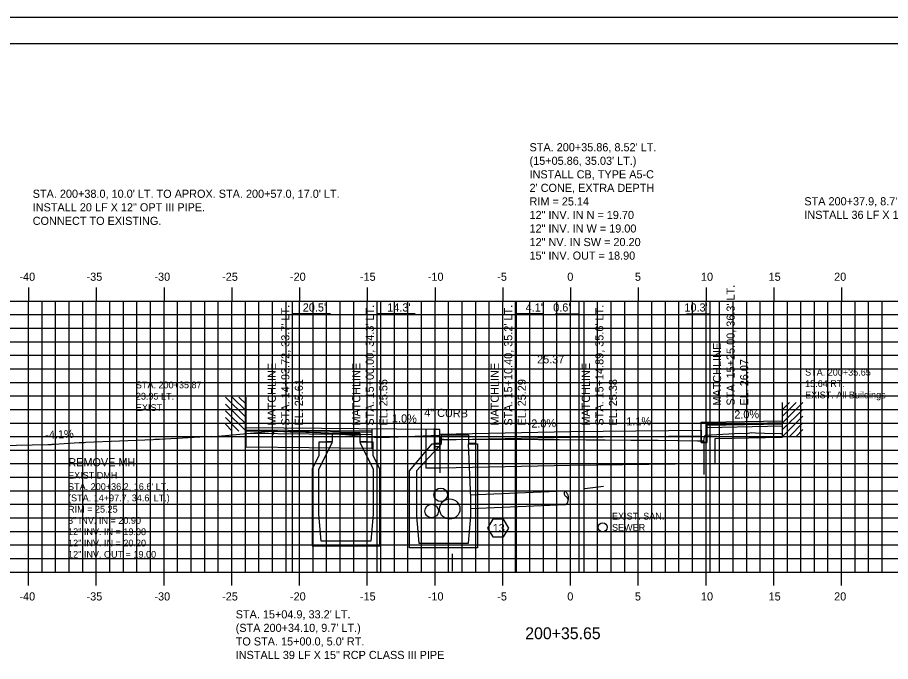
# Model space of a CAD drawing. Extents: x 1023237 to 1023407, y 394697 to 394807.
# Drawn here: x 1023278.8 to 1023343.3, y 394759 to 394806.5 of the extents above; entities that cross this region are included whole.
import ezdxf

# ---------------------------------------------------------------- set-up
doc = ezdxf.new("R2010")
doc.units = 0
for name, color, linetype in [('ANNOTATION', 7, 'Continuous'), ('BORDER', 7, 'Continuous'), ('D_Curb_Type_1_Lt', 7, 'Continuous'), ('D_Curb_Type_1_Rt', 7, 'Continuous'), ('D_Drainage_CB_Shape5_Lt', 7, 'Continuous'), ('D_Drainage_Culvert', 7, 'Continuous'), ('D_Drainage_Text', 7, 'Continuous'), ('D_Roadway_Centerline', 7, 'Continuous'), ('D_Roadway_Centerline_Text', 7, 'Continuous'), ('D_Roadway_Edge_TW', 7, 'Continuous'), ('D_Roadway_Sidewalks_Paved', 7, 'Continuous'), ('D_Roadway_SubGrade', 7, 'Continuous'), ('D_Text_Monospaced', 7, 'Continuous'), ('H_V ANNOTATION', 7, 'Continuous'), ('MAJOR', 7, 'Continuous'), ('MINOR', 7, 'Continuous'), ('PLOT BOUNDARY', 7, 'Continuous'), ('S_Buildings_SillElevation', 7, 'Continuous'), ('S_Roadway_Centerline', 7, 'Continuous'), ('S_Roadway_Edge_Pavement', 7, 'Continuous'), ('S_Utilities_UG_Sanitary_MH', 7, 'Continuous'), ('S_Utilities_UG_Sanitary_Sewer', 7, 'Continuous')]:
    doc.layers.add(name, color=color, linetype=linetype)

msp = doc.modelspace()

# ---------------------------------------------------------------- linework, layer by layer
at = {"layer": 'ANNOTATION'}
for p, q in [((1023299.149, 394765.607), (1023299.149, 394785.607)), ((1023305.384, 394765.607), (1023305.384, 394785.607)), ((1023315.6, 394765.607), (1023315.6, 394785.607)), ((1023320.296, 394765.607), (1023320.296, 394785.607)), ((1023329.979, 394765.607), (1023329.979, 394785.607)), ((1023301.955, 394784.658), (1023299.149, 394784.658)), ((1023308.19, 394784.658), (1023305.384, 394784.658)), ((1023317.591, 394784.658), (1023315.6, 394784.658)), ((1023318.531, 394784.658), (1023320.296, 394784.658)), ((1023328.214, 394784.658), (1023329.979, 394784.658)), ((1023322.088, 394771.909), (1023320.706, 394771.748)), ((1023310.935, 394766.95), (1023310.935, 394765.674))]:
    msp.add_line(p, q, dxfattribs=at)
at = {"layer": 'BORDER'}
msp.add_line((1023404.664, 394804.607), (1023244.664, 394804.607), dxfattribs=at)
at = {"layer": 'D_Curb_Type_1_Lt'}
msp.add_lwpolyline([(1023310.015, 394776.118), (1023309.599, 394776.118), (1023309.599, 394774.618), (1023310.015, 394774.618), (1023310.015, 394775.535), (1023310.015, 394776.118)], dxfattribs=at)
msp.add_lwpolyline([(1023310.015, 394776.118), (1023309.599, 394776.118), (1023309.599, 394774.618), (1023310.015, 394774.618), (1023310.015, 394775.535), (1023310.015, 394776.118)], dxfattribs=at)
msp.add_lwpolyline([(1023309.599, 394776.118), (1023309.599, 394774.618), (1023310.015, 394774.618), (1023310.015, 394776.118)], close=True, dxfattribs=at)
at = {"layer": 'D_Curb_Type_1_Rt'}
msp.add_lwpolyline([(1023329.309, 394776.668), (1023329.726, 394776.668), (1023329.726, 394775.168), (1023329.309, 394775.168), (1023329.309, 394776.084), (1023329.309, 394776.668)], dxfattribs=at)
msp.add_lwpolyline([(1023329.726, 394776.668), (1023329.726, 394775.168), (1023329.309, 394775.168), (1023329.309, 394776.668)], close=True, dxfattribs=at)
at = {"layer": 'D_Drainage_CB_Shape5_Lt'}
for points in [[(1023309.615, 394775.121), (1023310.14, 394775.121), (1023310.14, 394775.745), (1023312.141, 394775.745), (1023312.141, 394775.121), (1023312.633, 394775.121)], [(1023312.797, 394775.08), (1023312.797, 394767.402), (1023307.778, 394767.402), (1023307.778, 394773.077), (1023309.451, 394775.08), (1023310.14, 394775.08), (1023308.303, 394773.077), (1023308.303, 394769.732), (1023308.467, 394767.73), (1023312.141, 394767.73), (1023312.305, 394769.732), (1023312.305, 394771.077), (1023312.141, 394775.08), (1023312.797, 394775.08)]]:
    msp.add_lwpolyline(points, dxfattribs=at)
at = {"layer": 'D_Drainage_Culvert'}
for p, q in [((1023312.244, 394771.305), (1023319.24, 394771.592)), ((1023312.305, 394770.307), (1023319.301, 394770.593))]:
    msp.add_line(p, q, dxfattribs=at)
for centre, radius in [((1023310.084, 394771.307), 0.5), ((1023309.41, 394770.107), 0.5), ((1023310.747, 394770.257), 0.75)]:
    msp.add_circle(centre, radius, dxfattribs=at)
for centre, radius, start, end in [((1023319.477, 394771.426), 0.289, 145.08411, 241.23563), ((1023318.882, 394771.066), 0.636, 342.2646, 55.76139), ((1023319.153, 394770.893), 0.335, 296.14952, 56.63552)]:
    msp.add_arc(centre, radius, start, end, dxfattribs=at)
at = {"layer": 'D_Drainage_Text'}
msp.add_lwpolyline([(1023315.115, 394768.854), (1023314.718, 394769.503), (1023313.925, 394769.503), (1023313.528, 394768.854), (1023313.925, 394768.205), (1023314.718, 394768.205)], close=True, dxfattribs=at)
at = {"layer": 'D_Roadway_Edge_TW'}
for p, q in [((1023309.599, 394776.118), (1023295.715, 394776.255)), ((1023295.715, 394774.813), (1023295.715, 394776.255)), ((1023305.014, 394775.997), (1023295.715, 394776.089)), ((1023305.014, 394775.913), (1023295.715, 394776.005)), ((1023305.014, 394775.747), (1023295.715, 394775.839)), ((1023305.014, 394774.714), (1023305.014, 394776.157)), ((1023310.015, 394775.785), (1023319.663, 394775.982)), ((1023310.015, 394775.535), (1023310.015, 394775.785)), ((1023319.663, 394775.982), (1023329.309, 394776.084)), ((1023329.309, 394776.084), (1023329.309, 394775.834)), ((1023305.014, 394774.721), (1023295.715, 394774.813))]:
    msp.add_line(p, q, dxfattribs=at)
at = {"layer": 'D_Roadway_Sidewalks_Paved'}
for p, q in [((1023329.726, 394776.668), (1023335.307, 394776.779)), ((1023329.726, 394776.501), (1023329.726, 394776.668)), ((1023335.307, 394776.613), (1023329.726, 394776.501)), ((1023335.307, 394776.529), (1023329.726, 394776.418)), ((1023335.307, 394776.363), (1023329.726, 394776.251)), ((1023335.307, 394775.529), (1023330.309, 394775.429))]:
    msp.add_line(p, q, dxfattribs=at)
at = {"layer": 'D_Roadway_SubGrade'}
for p, q in [((1023309.599, 394776.201), (1023309.599, 394774.868)), ((1023329.726, 394776.501), (1023334.309, 394776.593)), ((1023329.726, 394775.168), (1023329.726, 394776.501)), ((1023305.015, 394775.157), (1023305.015, 394776.157)), ((1023309.015, 394773.265), (1023309.015, 394776.124)), ((1023310.015, 394775.368), (1023319.663, 394775.565)), ((1023310.015, 394774.868), (1023310.015, 394775.535)), ((1023310.015, 394775.535), (1023310.015, 394775.285)), ((1023319.663, 394775.565), (1023329.309, 394775.668)), ((1023329.309, 394775.584), (1023329.309, 394775.834)), ((1023329.309, 394775.834), (1023329.309, 394775.168)), ((1023329.309, 394775.168), (1023329.726, 394775.168)), ((1023330.309, 394775.429), (1023330.309, 394773.564)), ((1023309.599, 394774.868), (1023310.015, 394774.868)), ((1023310.015, 394773.285), (1023309.015, 394773.265)), ((1023319.663, 394773.482), (1023310.015, 394773.285)), ((1023329.309, 394773.584), (1023319.663, 394773.482)), ((1023330.309, 394773.564), (1023329.309, 394773.584))]:
    msp.add_line(p, q, dxfattribs=at)
at = {"layer": 'MAJOR'}
for p, q in [((1023279.663, 394786.609), (1023279.663, 394785.607)), ((1023284.663, 394786.609), (1023284.663, 394785.607)), ((1023289.663, 394786.609), (1023289.663, 394785.607)), ((1023294.663, 394786.609), (1023294.663, 394785.607)), ((1023299.663, 394786.609), (1023299.663, 394785.607)), ((1023304.663, 394786.609), (1023304.663, 394785.607)), ((1023309.663, 394786.609), (1023309.663, 394785.607)), ((1023314.663, 394786.609), (1023314.663, 394785.607)), ((1023319.663, 394786.609), (1023319.663, 394785.607)), ((1023324.663, 394786.609), (1023324.663, 394785.607)), ((1023329.663, 394786.609), (1023329.663, 394785.607)), ((1023334.663, 394786.609), (1023334.663, 394785.607)), ((1023339.663, 394786.609), (1023339.663, 394785.607)), ((1023249.663, 394785.607), (1023389.663, 394785.607)), ((1023279.663, 394765.607), (1023279.663, 394785.607)), ((1023284.663, 394765.607), (1023284.663, 394785.607)), ((1023289.663, 394765.607), (1023289.663, 394785.607)), ((1023294.663, 394765.607), (1023294.663, 394785.607)), ((1023299.663, 394765.607), (1023299.663, 394785.607)), ((1023304.663, 394765.607), (1023304.663, 394785.607)), ((1023309.663, 394765.607), (1023309.663, 394785.607)), ((1023314.663, 394765.607), (1023314.663, 394785.607)), ((1023319.663, 394765.607), (1023319.663, 394785.607)), ((1023324.663, 394765.607), (1023324.663, 394785.607)), ((1023329.663, 394765.607), (1023329.663, 394785.607)), ((1023334.663, 394765.607), (1023334.663, 394785.607)), ((1023339.663, 394765.607), (1023339.663, 394785.607)), ((1023249.663, 394780.607), (1023389.663, 394780.607)), ((1023249.663, 394775.607), (1023389.663, 394775.607)), ((1023249.663, 394770.607), (1023389.663, 394770.607)), ((1023249.663, 394765.607), (1023389.663, 394765.607)), ((1023279.663, 394764.605), (1023279.663, 394765.607)), ((1023284.663, 394764.605), (1023284.663, 394765.607)), ((1023289.663, 394764.605), (1023289.663, 394765.607)), ((1023294.663, 394764.605), (1023294.663, 394765.607)), ((1023299.663, 394764.605), (1023299.663, 394765.607)), ((1023304.663, 394764.605), (1023304.663, 394765.607)), ((1023309.663, 394764.605), (1023309.663, 394765.607)), ((1023314.663, 394764.605), (1023314.663, 394765.607)), ((1023319.663, 394764.605), (1023319.663, 394765.607)), ((1023324.663, 394764.605), (1023324.663, 394765.607)), ((1023329.663, 394764.605), (1023329.663, 394765.607)), ((1023334.663, 394764.605), (1023334.663, 394765.607)), ((1023339.663, 394764.605), (1023339.663, 394765.607))]:
    msp.add_line(p, q, dxfattribs=at)
at = {"layer": 'MINOR'}
for p, q in [((1023280.663, 394765.607), (1023280.663, 394785.607)), ((1023281.663, 394765.607), (1023281.663, 394785.607)), ((1023282.663, 394765.607), (1023282.663, 394785.607)), ((1023283.663, 394765.607), (1023283.663, 394785.607)), ((1023285.663, 394765.607), (1023285.663, 394785.607)), ((1023286.663, 394765.607), (1023286.663, 394785.607)), ((1023287.663, 394765.607), (1023287.663, 394785.607)), ((1023288.663, 394765.607), (1023288.663, 394785.607)), ((1023290.663, 394765.607), (1023290.663, 394785.607)), ((1023291.663, 394765.607), (1023291.663, 394785.607)), ((1023292.663, 394765.607), (1023292.663, 394785.607)), ((1023293.663, 394765.607), (1023293.663, 394785.607)), ((1023295.663, 394765.607), (1023295.663, 394785.607)), ((1023296.663, 394765.607), (1023296.663, 394785.607)), ((1023297.663, 394765.607), (1023297.663, 394785.607)), ((1023298.663, 394765.607), (1023298.663, 394785.607)), ((1023300.663, 394765.607), (1023300.663, 394785.607)), ((1023301.663, 394765.607), (1023301.663, 394785.607)), ((1023302.663, 394765.607), (1023302.663, 394785.607)), ((1023303.663, 394765.607), (1023303.663, 394785.607)), ((1023305.663, 394765.607), (1023305.663, 394785.607)), ((1023306.663, 394765.607), (1023306.663, 394785.607)), ((1023307.663, 394765.607), (1023307.663, 394785.607)), ((1023308.663, 394765.607), (1023308.663, 394785.607)), ((1023310.663, 394765.607), (1023310.663, 394785.607)), ((1023311.663, 394765.607), (1023311.663, 394785.607)), ((1023312.663, 394765.607), (1023312.663, 394785.607)), ((1023313.663, 394765.607), (1023313.663, 394785.607)), ((1023315.663, 394765.607), (1023315.663, 394785.607)), ((1023316.663, 394765.607), (1023316.663, 394785.607)), ((1023317.663, 394765.607), (1023317.663, 394785.607)), ((1023318.663, 394765.607), (1023318.663, 394785.607)), ((1023320.663, 394765.607), (1023320.663, 394785.607)), ((1023321.663, 394765.607), (1023321.663, 394785.607)), ((1023322.663, 394765.607), (1023322.663, 394785.607)), ((1023323.663, 394765.607), (1023323.663, 394785.607)), ((1023325.663, 394765.607), (1023325.663, 394785.607)), ((1023326.663, 394765.607), (1023326.663, 394785.607)), ((1023327.663, 394765.607), (1023327.663, 394785.607)), ((1023328.663, 394765.607), (1023328.663, 394785.607)), ((1023330.663, 394765.607), (1023330.663, 394785.607)), ((1023331.663, 394765.607), (1023331.663, 394785.607)), ((1023332.663, 394765.607), (1023332.663, 394785.607)), ((1023333.663, 394765.607), (1023333.663, 394785.607)), ((1023335.663, 394765.607), (1023335.663, 394785.607)), ((1023336.663, 394765.607), (1023336.663, 394785.607)), ((1023337.663, 394765.607), (1023337.663, 394785.607)), ((1023338.663, 394765.607), (1023338.663, 394785.607)), ((1023340.663, 394765.607), (1023340.663, 394785.607)), ((1023341.663, 394765.607), (1023341.663, 394785.607)), ((1023342.663, 394765.607), (1023342.663, 394785.607)), ((1023249.663, 394784.607), (1023389.663, 394784.607)), ((1023249.663, 394783.607), (1023389.663, 394783.607)), ((1023249.663, 394782.607), (1023389.663, 394782.607)), ((1023249.663, 394781.607), (1023389.663, 394781.607)), ((1023249.663, 394779.607), (1023389.663, 394779.607)), ((1023249.663, 394778.607), (1023389.663, 394778.607)), ((1023249.663, 394777.607), (1023389.663, 394777.607)), ((1023249.663, 394776.607), (1023389.663, 394776.607)), ((1023249.663, 394774.607), (1023389.663, 394774.607)), ((1023249.663, 394773.607), (1023389.663, 394773.607)), ((1023249.663, 394772.607), (1023389.663, 394772.607)), ((1023249.663, 394771.607), (1023389.663, 394771.607)), ((1023249.663, 394769.607), (1023389.663, 394769.607)), ((1023249.663, 394768.607), (1023389.663, 394768.607)), ((1023249.663, 394767.607), (1023389.663, 394767.607)), ((1023249.663, 394766.607), (1023389.663, 394766.607))]:
    msp.add_line(p, q, dxfattribs=at)
at = {"layer": 'PLOT BOUNDARY'}
msp.add_lwpolyline([(1023236.57, 394696.548), (1023406.57, 394696.548), (1023406.57, 394806.548), (1023236.57, 394806.548)], close=True, dxfattribs=at)
at = {"layer": 'S_Buildings_SillElevation'}
for p, q in [((1023295.715, 394777.019), (1023294.206, 394778.528)), ((1023295.715, 394777.511), (1023294.698, 394778.528)), ((1023295.715, 394778.003), (1023295.19, 394778.528)), ((1023295.715, 394776.002), (1023295.715, 394778.528)), ((1023335.307, 394775.607), (1023335.307, 394778.133)), ((1023335.307, 394776.624), (1023336.816, 394778.133)), ((1023335.307, 394777.116), (1023336.324, 394778.133)), ((1023335.307, 394777.608), (1023335.832, 394778.133)), ((1023295.715, 394776.527), (1023294.206, 394778.003)), ((1023295.715, 394776.002), (1023294.206, 394777.511)), ((1023335.307, 394776.132), (1023336.816, 394777.608)), ((1023295.19, 394776.002), (1023294.206, 394777.019)), ((1023335.307, 394775.607), (1023336.816, 394777.116)), ((1023294.698, 394776.002), (1023294.206, 394776.527)), ((1023335.832, 394775.607), (1023336.816, 394776.624)), ((1023336.324, 394775.607), (1023336.816, 394776.132))]:
    msp.add_line(p, q, dxfattribs=at)
at = {"layer": 'S_Roadway_Centerline'}
msp.add_lwpolyline([(1023275.244, 394774.892), (1023281.097, 394775.028), (1023281.202, 394775.03), (1023281.204, 394775.03), (1023281.343, 394775.033), (1023281.344, 394775.033), (1023281.403, 394775.037), (1023281.437, 394775.039), (1023281.545, 394775.046), (1023283.396, 394775.162), (1023283.774, 394775.179), (1023283.902, 394775.184), (1023288.867, 394775.402), (1023288.972, 394775.407), (1023289.317, 394775.423), (1023293.139, 394775.63), (1023293.14, 394775.599), (1023293.244, 394775.612), (1023293.378, 394775.619), (1023293.504, 394775.622), (1023293.529, 394775.623), (1023293.666, 394775.628), (1023297.635, 394775.997), (1023297.693, 394776.003), (1023297.693, 394775.801), (1023297.759, 394775.803), (1023297.759, 394776.004), (1023298.028, 394776.003), (1023298.969, 394775.969), (1023299.566, 394775.947), (1023302.375, 394775.844), (1023304.669, 394775.583), (1023305.682, 394775.53), (1023307.546, 394775.616), (1023309.977, 394775.718), (1023310.015, 394775.424), (1023310.03, 394775.423), (1023310.282, 394775.414), (1023311.06, 394775.391), (1023311.102, 394775.389), (1023313.244, 394775.404), (1023317.309, 394775.388), (1023318.818, 394775.396), (1023320.803, 394775.378), (1023322.217, 394775.362), (1023324.111, 394775.336), (1023326.127, 394775.33), (1023329.023, 394775.301), (1023329.498, 394775.302), (1023329.542, 394775.585), (1023329.597, 394775.723), (1023332.207, 394775.857), (1023332.619, 394775.837), (1023333.033, 394775.898), (1023333.309, 394775.889), (1023333.98, 394775.867), (1023335.158, 394775.828), (1023335.249, 394775.827), (1023335.307, 394775.826)], dxfattribs=at)
at = {"layer": 'S_Roadway_Edge_Pavement'}
for p, q in [((1023310.015, 394775.424), (1023310.015, 394772.924)), ((1023329.498, 394775.302), (1023329.498, 394772.802))]:
    msp.add_line(p, q, dxfattribs=at)
at = {"layer": 'S_Utilities_UG_Sanitary_MH'}
for p, q in [((1023301.087, 394773.193), (1023302.105, 394775.194)), ((1023302.105, 394775.194), (1023301.087, 394775.194)), ((1023301.087, 394775.194), (1023301.087, 394774.21)), ((1023305.09, 394775.194), (1023304.106, 394775.194)), ((1023304.106, 394775.194), (1023305.09, 394773.193)), ((1023305.09, 394774.21), (1023305.09, 394775.194)), ((1023301.087, 394774.21), (1023300.595, 394773.193)), ((1023305.582, 394773.193), (1023305.09, 394774.21)), ((1023300.595, 394773.193), (1023300.595, 394767.55)), ((1023301.087, 394769.879), (1023301.087, 394773.193)), ((1023305.09, 394773.193), (1023305.09, 394769.879)), ((1023305.582, 394767.55), (1023305.582, 394773.193)), ((1023301.251, 394767.878), (1023301.087, 394769.879)), ((1023305.09, 394769.879), (1023304.926, 394767.878)), ((1023304.926, 394767.878), (1023301.251, 394767.878)), ((1023300.595, 394767.55), (1023305.582, 394767.55))]:
    msp.add_line(p, q, dxfattribs=at)
msp.add_lwpolyline([(1023301.612, 394775.236), (1023302.105, 394775.236), (1023302.105, 394775.859), (1023304.106, 394775.859), (1023304.106, 394775.236), (1023304.598, 394775.236)], dxfattribs=at)
at = {"layer": 'S_Utilities_UG_Sanitary_Sewer'}
msp.add_circle((1023322.035, 394768.91), 0.333, dxfattribs=at)

# ---------------------------------------------------------------- texts
at = {"layer": 'ANNOTATION'}
for s, rotation, p in [("STA. 15+25.00, 36.3' LT.", 90, (1023331.776, 394777.893)), ("STA. 14+93.72, 33.7' LT.", 90, (1023298.912, 394776.415)), ("STA. 15+00.00, 34.3' LT.", 90, (1023305.147, 394776.415)), ("STA. 15+10.40, 35.2' LT.", 90, (1023315.363, 394776.415)), ("STA. 15+14.89, 35.6' LT.", 90, (1023322.093, 394776.415)), ('MATCHLINE', 90, (1023330.776, 394777.893)), ('MATCHLINE', 90, (1023297.912, 394776.415)), ('MATCHLINE', 90, (1023304.147, 394776.415)), ('MATCHLINE', 90, (1023314.363, 394776.415)), ('MATCHLINE', 90, (1023321.093, 394776.415)), ('EL. 26.07', 90, (1023332.776, 394777.893)), ('EL. 25.61', 90, (1023299.912, 394776.415)), ('EL. 25.55', 90, (1023306.147, 394776.415)), ('EL. 25.29', 90, (1023316.363, 394776.415)), ('EL. 25.38', 90, (1023323.093, 394776.415)), ('4" CURB', 358.85424, (1023308.856, 394777.081)), ('2.0%', 1.14576, (1023331.753, 394776.929)), ('1.0%', 358.85424, (1023306.482, 394776.664)), ('-2.0%', 1.16993, (1023316.504, 394776.259)), ('1.1%', 0.60986, (1023323.78, 394776.425)), ('-4.1%', 2.37375, (1023280.909, 394775.431))]:
    msp.add_text(s, height=0.6, rotation=rotation, dxfattribs=at).set_placement(p)
for s, p in [("20.5'", (1023299.901, 394784.839)), ("14.3'", (1023306.136, 394784.839)), ("4.1'", (1023316.352, 394784.839)), ("0.6'", (1023318.384, 394784.839)), ("10.3'", (1023328.067, 394784.839))]:
    msp.add_text(s, height=0.6, dxfattribs=at).set_placement(p)
at = {"layer": 'D_Drainage_Text'}
for s, p in [("STA. 200+35.86, 8.52' LT.", (1023316.635, 394796.667)), ("(15+05.86, 35.03' LT.)", (1023316.635, 394795.667)), ('INSTALL CB, TYPE A5-C', (1023316.635, 394794.667)), ("2' CONE, EXTRA DEPTH", (1023316.635, 394793.667)), ("STA. 200+38.0, 10.0' LT. TO APROX. STA. 200+57.0, 17.0' LT.", (1023279.969, 394793.232)), ('RIM = 25.14', (1023316.635, 394792.667)), ("STA 200+37.9, 8.7' LT. TO STA 200+68.6, 8.4' RT.", (1023336.918, 394792.679)), ('INSTALL 20 LF X 12" OPT III PIPE.', (1023279.969, 394792.232)), ('INSTALL 36 LF X 12" OPT III PIPE', (1023336.918, 394791.679)), ('CONNECT TO EXISTING.', (1023279.969, 394791.232)), ('12" INV. IN N = 19.70', (1023316.635, 394791.667)), ('12" INV. IN W = 19.00', (1023316.635, 394790.667)), ('12" NV. IN SW = 20.20', (1023316.635, 394789.667)), ('15" INV. OUT = 18.90', (1023316.635, 394788.667)), ('REMOVE MH', (1023282.596, 394773.413)), ('13', (1023313.923, 394768.554)), ("STA. 15+04.9, 33.2' LT. ", (1023294.951, 394762.185)), ("(STA 200+34.10, 9.7' LT.)", (1023294.951, 394761.185)), ("TO STA. 15+00.0, 5.0' RT.", (1023294.951, 394760.185)), ('INSTALL 39 LF X 15" RCP CLASS III PIPE', (1023294.951, 394759.185))]:
    msp.add_text(s, height=0.6, dxfattribs=at).set_placement(p)
at = {"layer": 'D_Roadway_Centerline'}
for s, p in [('C', (1023319.658, 394775.982)), ('L', (1023319.663, 394775.974))]:
    msp.add_text(s, height=0.0146, dxfattribs=at).set_placement(p)
at = {"layer": 'D_Roadway_Centerline_Text'}
msp.add_text('25.37', height=0.6, dxfattribs=at).set_placement((1023317.195, 394781.008))
at = {"layer": 'D_Text_Monospaced'}
for s, height, p in [('STA. 200+35.65', 0.49998, (1023336.973, 394780.105)), ('STA. 200+35.87', 0.49998, (1023287.583, 394779.17)), ('15.64 RT.', 0.5, (1023336.973, 394779.271)), ('23.95 LT.', 0.5, (1023287.583, 394778.336)), ('EXIST. All Buildings', 0.49998, (1023336.973, 394778.431)), ('EXIST. ', 0.5, (1023287.583, 394777.496)), ('EXIST DMH', 0.5, (1023282.577, 394772.496)), ("STA. 200+36.2, 16.6' LT.", 0.49998, (1023282.577, 394771.663)), ("(STA. 14+97.7, 34.6' LT.)", 0.49998, (1023282.577, 394770.83)), ('RIM = 25.25', 0.49998, (1023282.577, 394769.996)), ('EXIST. SAN.', 0.49998, (1023322.722, 394769.482)), ('8" INV. IN = 20.90', 0.49998, (1023282.577, 394769.163)), ('SEWER', 0.5, (1023322.722, 394768.649)), ('12" INV. IN = 19.00', 0.49998, (1023282.577, 394768.33)), ('12" INV. IN = 20.20', 0.49998, (1023282.577, 394767.496)), ('12" INV. OUT = 19.00', 0.49998, (1023282.577, 394766.663))]:
    msp.add_text(s, height=height, dxfattribs=at).set_placement(p)
at = {"layer": 'H_V ANNOTATION'}
for s, height, p in [('-40', 0.6, (1023278.989, 394787.107)), ('-35', 0.6, (1023283.944, 394787.107)), ('-30', 0.6, (1023288.952, 394787.107)), ('-25', 0.6, (1023293.949, 394787.107)), ('-20', 0.6, (1023298.957, 394787.107)), ('-15', 0.6, (1023304.12, 394787.107)), ('-10', 0.6, (1023309.128, 394787.107)), ('-5', 0.6, (1023314.254, 394787.107)), ('0', 0.6, (1023319.422, 394787.107)), ('5', 0.6, (1023324.414, 394787.107)), ('10', 0.6, (1023329.289, 394787.107)), ('15', 0.6, (1023334.281, 394787.107)), ('20', 0.6, (1023339.117, 394787.107)), ('-40', 0.6, (1023278.989, 394763.507)), ('-35', 0.6, (1023283.944, 394763.507)), ('-30', 0.6, (1023288.952, 394763.507)), ('-25', 0.6, (1023293.949, 394763.507)), ('-20', 0.6, (1023298.957, 394763.507)), ('-15', 0.6, (1023304.12, 394763.507)), ('-10', 0.6, (1023309.128, 394763.507)), ('-5', 0.6, (1023314.254, 394763.507)), ('0', 0.6, (1023319.422, 394763.507)), ('5', 0.6, (1023324.414, 394763.507)), ('10', 0.6, (1023329.289, 394763.507)), ('15', 0.6, (1023334.281, 394763.507)), ('20', 0.6, (1023339.117, 394763.507)), ('200+35.65', 0.875, (1023316.32, 394760.65))]:
    msp.add_text(s, height=height, dxfattribs=at).set_placement(p)

doc.saveas('drawing.dxf')
